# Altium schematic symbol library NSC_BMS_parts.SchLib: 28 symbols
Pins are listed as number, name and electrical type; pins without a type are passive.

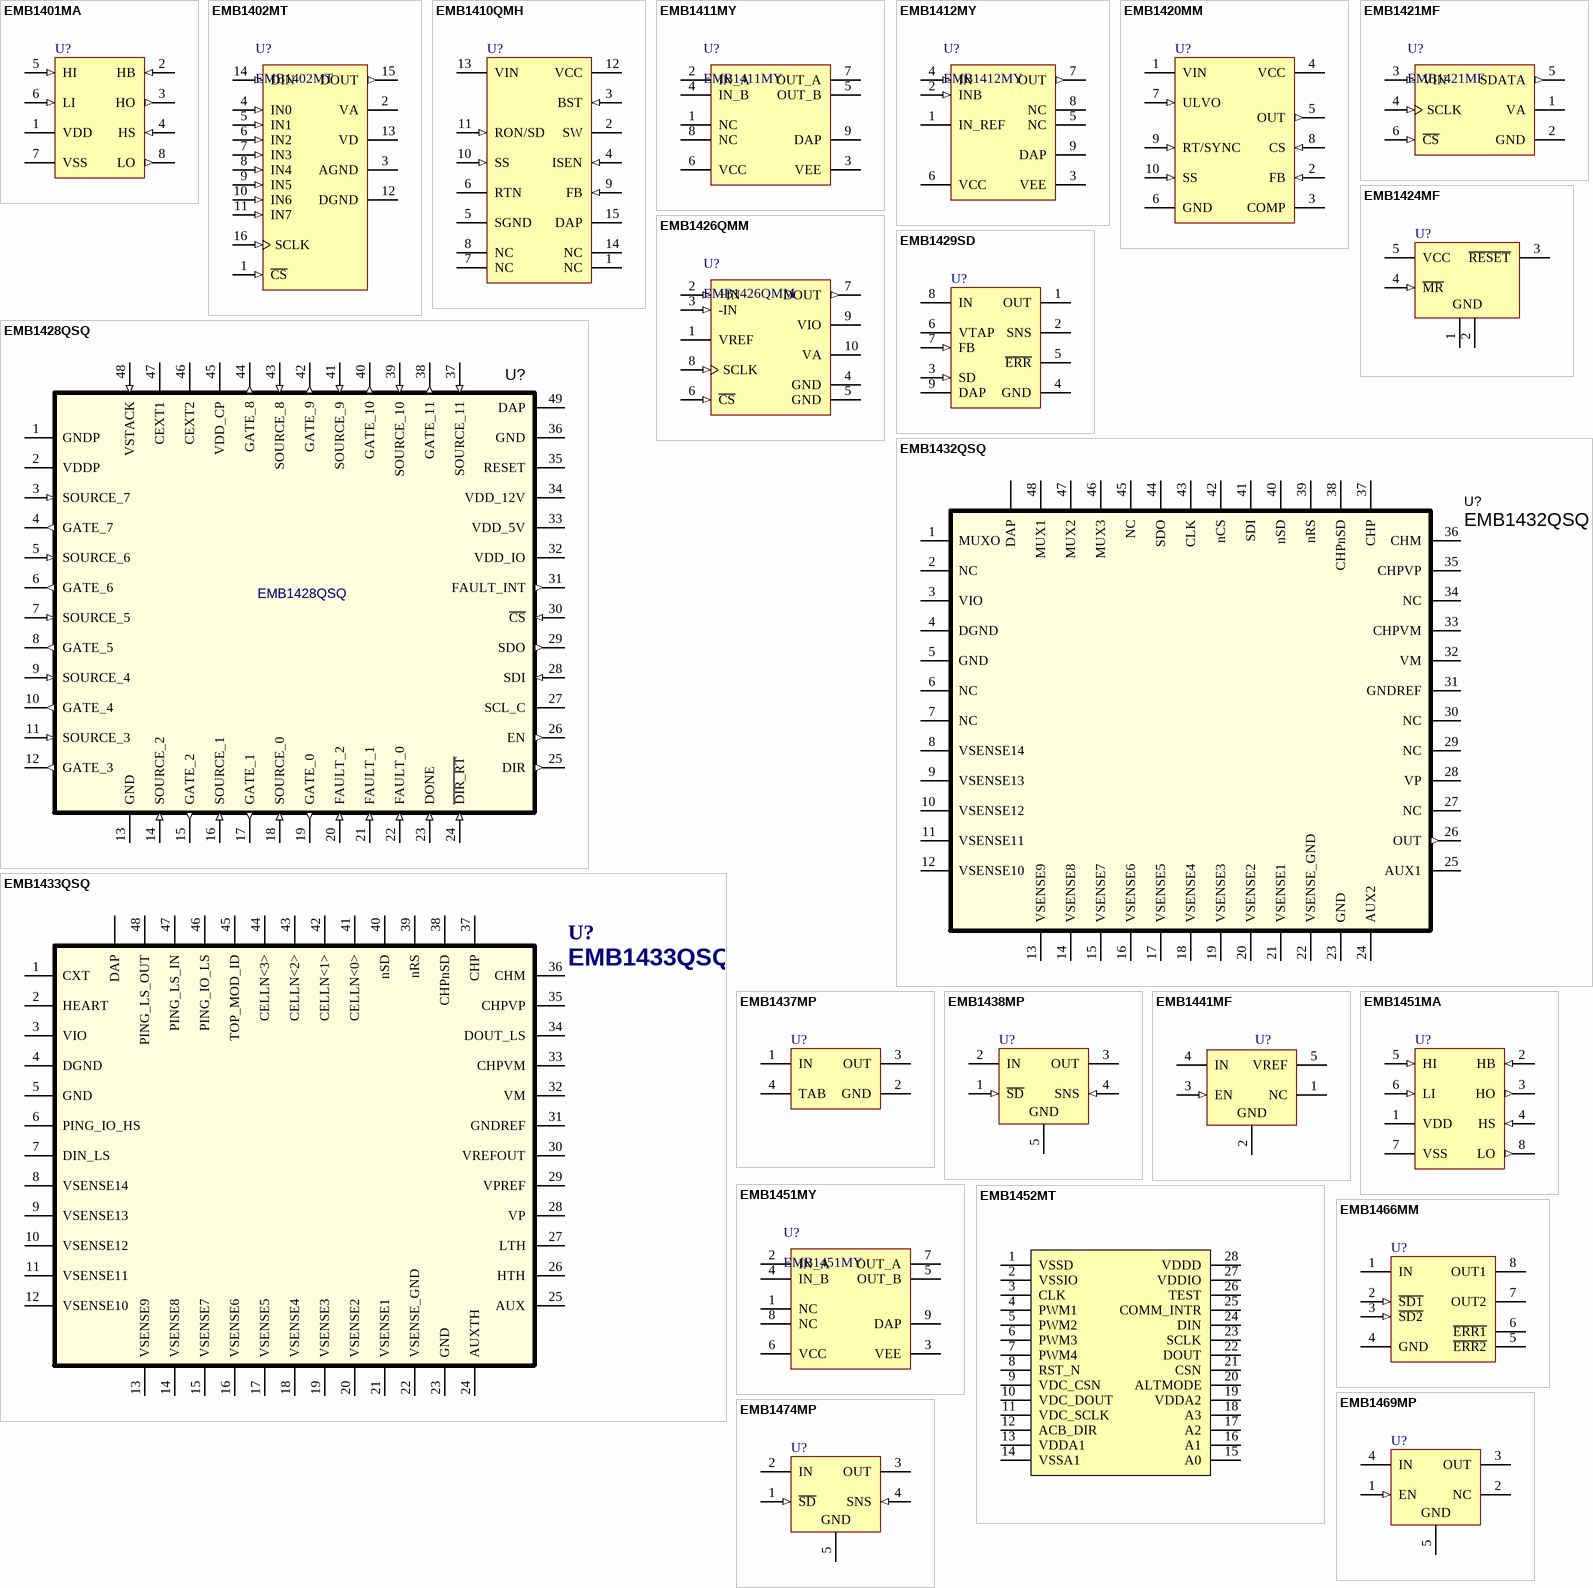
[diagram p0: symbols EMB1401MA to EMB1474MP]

## EMB1401MA
designator U?
3A High Voltage High-Side and Low-Side Gate Driver; PartNumber: EMB1401MA; Manufacturer: National Semiconductor; CompType: Switcher
footprint M08A_N (SOIC, 8-Leads, Body 4.9x3.9mm, Pitch 1.27mm, IPC Medium Density)
footprint M08A_L (SOIC, 8-Leads, Body 4.9x3.9mm, Pitch 1.27mm, IPC High Density)
footprint M08A_M (SOIC, 8-Leads, Body 4.9x3.9mm, Pitch 1.27mm, IPC Low Density)
pins: 1 VDD (power), 2 HB (in), 3 HO (out), 4 HS (in), 5 HI (in), 6 LI (in), 7 VSS (power), 8 LO (out)

## EMB1402MT
designator U?
8-Channel, 500 kSPS to 1 MSPS, 12-Bit A/D Converter; Manufacturer: National Semiconductor; CompType: ADC IC; PowerWise: Y
footprint MTC16_N (TSOP, 16-Leads, Body 5x4.4mm, Pitch 0.65mm, IPC Medium Density)
footprint MTC16_L (TSOP, 16-Leads, Body 5x4.4mm, Pitch 0.65mm, IPC High Density)
footprint MTC16_M (TSOP, 16-Leads, Body 5x4.4mm, Pitch 0.65mm, IPC Low Density)
pins: 1 ~{CS} (in), 2 VA (power), 3 AGND (power), 4 IN0 (in), 5 IN1 (in), 6 IN2 (in), 7 IN3 (in), 8 IN4 (in), 9 IN5 (in), 10 IN6 (in), 11 IN7 (in), 12 DGND (power), 13 VD (power), 14 DIN (in), 15 DOUT (out), 16 SCLK (in)

## EMB1410QMH
designator U?
High Voltage 1A Step Down Switching Regulator; PartNumber: EMB1410QMH; Manufacturer: National Semiconductor; CompType: Switcher
footprint MXA14A_N (TSOP, 14-Leads, Body 5x4.4mm, Pitch 0.65mm, Exposed Pad, IPC Medium Density)
footprint MXA14A_L (TSOP, 14-Leads, Body 5x4.4mm, Pitch 0.65mm, Exposed Pad, IPC High Density)
footprint MXA14A_M (TSOP, 14-Leads, Body 5x4.4mm, Pitch 0.65mm, Exposed Pad, IPC Low Density)
pins: 1 NC, 2 SW (power), 3 BST (in), 4 ISEN (in), 5 SGND (power), 6 RTN (power), 7 NC, 8 NC, 9 FB (in), 10 SS (in), 11 RON/SD (in), 12 VCC (power), 13 VIN (power), 14 NC, 15 DAP (power)

## EMB1411MY
designator U?
Dual 5A Compound Gate Driver; Manufacturer: National Semiconductor; CompType: Switcher; PackageTopMarking: ZXTT*SSYB; PowerWise: N
footprint MUY08A_N (TSOP, 8-Leads, Body 3x3mm, Pitch 0.65mm, Exposed Pad, IPC Medium Density)
footprint MUY08A_L (TSOP, 8-Leads, Body 3x3mm, Pitch 0.65mm, Exposed Pad, IPC High Density)
footprint MUY08A_M (TSOP, 8-Leads, Body 3x3mm, Pitch 0.65mm, Exposed Pad, IPC Low Density)
pins: 1 NC, 2 IN_A (power), 3 VEE (power), 4 IN_B (power), 5 OUT_B (power), 6 VCC (power), 7 OUT_A (power), 8 NC, 9 DAP (power)

## EMB1412MY
designator U?
Dual 5A Compound Gate Driver; Manufacturer: National Semiconductor; CompType: Switcher; PowerWise: N
footprint MUY08A_N (TSOP, 8-Leads, Body 3x3mm, Pitch 0.65mm, Exposed Pad, IPC Medium Density)
footprint MUY08A_L (TSOP, 8-Leads, Body 3x3mm, Pitch 0.65mm, Exposed Pad, IPC High Density)
footprint MUY08A_M (TSOP, 8-Leads, Body 3x3mm, Pitch 0.65mm, Exposed Pad, IPC Low Density)
pins: 1 IN_REF (power), 2 INB (in), 3 VEE (power), 4 IN (in), 5 NC, 6 VCC (power), 7 OUT (out), 8 NC, 9 DAP (power)

## EMB1420MM
designator U?
100V Current Mode PWM Controller; PartNumber: EMB1420MM; Manufacturer: National Semiconductor; CompType: Switcher
footprint MUB10A_N (TSSOP, 10-Leads, Body 3x3mm, Pitch 0.5mm, IPC Medium Density)
footprint MUB10A_L (TSSOP, 10-Leads, Body 3x3mm, Pitch 0.5mm, IPC High Density)
footprint MUB10A_M (TSSOP, 10-Leads, Body 3x3mm, Pitch 0.5mm, IPC Low Density)
pins: 1 VIN (power), 2 FB (in), 3 COMP, 4 VCC (power), 5 OUT (out), 6 GND (power), 7 ULVO (in), 8 CS (in), 9 RT/SYNC (in), 10 SS (in)

## EMB1421MF
designator U?
1MSPS, 12-Bit A/D Converter in SOT-23; Manufacturer: National Semiconductor; CompType: ADC IC; PowerWise: Y
footprint MF06A_N (SOT23, 6-Leads, Body 2.9x1.6mm, Pitch 0.95mm, Lead Span 2.8mm, IPC Medium Density)
footprint MF06A_L (SOT23, 6-Leads, Body 2.9x1.6mm, Pitch 0.95mm, Lead Span 2.8mm, IPC High Density)
footprint MF06A_M (SOT23, 6-Leads, Body 2.9x1.6mm, Pitch 0.95mm, Lead Span 2.8mm, IPC Low Density)
pins: 1 VA (power), 2 GND (power), 3 VIN (in), 4 SCLK (in), 5 SDATA (out), 6 ~{CS} (in)

## EMB1424MF
designator U?
5-Pin Microprocessor Reset Circuits; PartNumber: EMB1424MF; Manufacturer: National Semiconductor; CompType: MiscPower; PowerWise: N
footprint MF05A_N (SOT23, 5-Leads, Body 2.9x1.6mm, Pitch 0.95mm, Lead Span 2.8mm, IPC Medium Density)
footprint MF05A_L (SOT23, 5-Leads, Body 2.9x1.6mm, Pitch 0.95mm, Lead Span 2.8mm, IPC High Density)
footprint MF05A_M (SOT23, 5-Leads, Body 2.9x1.6mm, Pitch 0.95mm, Lead Span 2.8mm, IPC Low Density)
pins: 1 GND (power), 2 GND (power), 3 ~{RESET} (oc), 4 ~{MR} (in), 5 VCC (power)

## EMB1426QMM
designator U?
14-Bit, 50 kSPS to 250 kSPS, Differential Input, Micro Power A/D Converter; Manufacturer: National Semiconductor; CompType: ADC IC; PowerWise: Y
footprint MUB10A_N (TSSOP, 10-Leads, Body 3x3mm, Pitch 0.5mm, IPC Medium Density)
footprint MUB10A_L (TSSOP, 10-Leads, Body 3x3mm, Pitch 0.5mm, IPC High Density)
footprint MUB10A_M (TSSOP, 10-Leads, Body 3x3mm, Pitch 0.5mm, IPC Low Density)
pins: 1 VREF (power), 2 +IN (in), 3 -IN (in), 4 GND (power), 5 GND (power), 6 ~{CS} (in), 7 DOUT (out), 8 SCLK (in), 9 VIO (power), 10 VA (power)

## EMB1428QSQ
designator U?
12 channel Gate Controller; Manufacturer: National Semiconductor
footprint sqa48a (QFN, 48-Leads, Body 7x7mm, Pitch 0.5mm, NSC Recommended)
pins: 1 GNDP, 2 VDDP (power), 3 SOURCE_7 (in), 4 GATE_7 (out), 5 SOURCE_6 (in), 6 GATE_6 (out), 7 SOURCE_5 (in), 8 GATE_5 (out), 9 SOURCE_4 (in), 10 GATE_4 (out), 11 SOURCE_3 (in), 12 GATE_3 (out), 13 GND (power), 14 SOURCE_2 (in), 15 GATE_2 (out), 16 SOURCE_1 (in), 17 GATE_1 (out), 18 SOURCE_0 (in), 19 GATE_0 (out), 20 FAULT_2 (in), 21 FAULT_1 (in), 22 FAULT_0 (in), 23 DONE (in), 24 ~{DIR_RT} (in), 25 DIR (out), 26 EN (out), 27 SCL_C, 28 SDI (in), 29 SDO (out), 30 ~{CS} (in), 31 FAULT_INT (out), 32 VDD_IO (power), 33 VDD_5V (power), 34 VDD_12V (power), 35 RESET, 36 GND (power), 37 SOURCE_11 (in), 38 GATE_11 (out), 39 SOURCE_10 (in), 40 GATE_10 (out), 41 SOURCE_9 (in), 42 GATE_9 (out), 43 SOURCE_8 (in), 44 GATE_8 (out), 45 VDD_CP (power), 46 CEXT2, 47 CEXT1, 48 VSTACK (in), 49 DAP

## EMB1429SD
designator U?
Series of Adjustable Micropower Voltage Regulators; PartNumber: EMB1429SD; Manufacturer: National Semiconductor; CompType: LDO IC
footprint SDC08A (SON, 8-Leads, Body 4x4mm, Pitch 0.8mm, NSC Recommended)
pins: 1 OUT (power), 2 SNS, 3 SD (in), 4 GND (power), 5 ~{ERR} (oc), 6 VTAP, 7 FB (in), 8 IN (power), 9 DAP (power)

## EMB1432QSQ
designator U?
14 channel AFE; Manufacturer: National Semiconductor; CompType: Used in BOM report; SymbolCreator: cwiosc
footprint SQA48B (QFN, 48-Leads, Body 7x7mm, Pitch 0.5mm, NSC Recommended)
pins: 1 MUXO, 2 NC, 3 VIO, 4 DGND, 5 GND, 6 NC, 7 NC, 8 VSENSE14, 9 VSENSE13, 10 VSENSE12, 11 VSENSE11, 12 VSENSE10, 13 VSENSE9, 14 VSENSE8, 15 VSENSE7, 16 VSENSE6, 17 VSENSE5, 18 VSENSE4, 19 VSENSE3, 20 VSENSE2, 21 VSENSE1, 22 VSENSE_GND, 23 GND, 24 AUX2, 25 AUX1, 26 OUT (out), 27 NC, 28 VP, 29 NC, 30 NC, 31 GNDREF, 32 VM, 33 CHPVM, 34 NC, 35 CHPVP, 36 CHM, 37 CHP, 38 CHPnSD, 39 nRS, 40 nSD, 41 SDI, 42 nCS, 43 CLK, 44 SDO, 45 NC, 46 MUX3, 47 MUX2, 48 MUX1, 49 DAP

## EMB1433QSQ
designator U?
Battery Stack Protection WCOMP; Manufacturer: National Semiconductor; CompType: Used in BOM report; SymbolVersion: 100509; SymbolCreator: cwiosc
footprint sqa48b (QFN, 48-Leads, Body 7x7mm, Pitch 0.5mm, NSC Recommended)
pins: 1 CXT, 2 HEART, 3 VIO, 4 DGND, 5 GND, 6 PING_IO_HS, 7 DIN_LS, 8 VSENSE14, 9 VSENSE13, 10 VSENSE12, 11 VSENSE11, 12 VSENSE10, 13 VSENSE9, 14 VSENSE8, 15 VSENSE7, 16 VSENSE6, 17 VSENSE5, 18 VSENSE4, 19 VSENSE3, 20 VSENSE2, 21 VSENSE1, 22 VSENSE_GND, 23 GND, 24 AUXTH, 25 AUX, 26 HTH, 27 LTH, 28 VP, 29 VPREF, 30 VREFOUT, 31 GNDREF, 32 VM, 33 CHPVM, 34 DOUT_LS, 35 CHPVP, 36 CHM, 37 CHP, 38 CHPnSD, 39 nRS, 40 nSD, 41 CELLN<0>, 42 CELLN<1>, 43 CELLN<2>, 44 CELLN<3>, 45 TOP_MOD_ID, 46 PING_IO_LS, 47 PING_LS_IN, 48 PING_LS_OUT, 49 DAP

## EMB1437MP
designator U?
500 mA Low Dropout Regulator; PartNumber: EMB1437MP; Manufacturer: National Semiconductor; CompType: LDO IC; PowerWise: N
footprint MP04A_N (SOT223, 4-Leads, Body 6.5x3.5mm, Pitch 2.3mm, Lead Span 7mm, IPC Medium Density)
footprint MP04A_L (SOT223, 4-Leads, Body 6.5x3.5mm, Pitch 2.3mm, Lead Span 7mm, IPC High Density)
footprint MP04A_M (SOT223, 4-Leads, Body 6.5x3.5mm, Pitch 2.3mm, Lead Span 7mm, IPC Low Density)
pins: 1 IN (power), 2 GND (power), 3 OUT (power), 4 TAB (power)

## EMB1438MP
designator U?
0.8A Fast Ultra Low Dropout Linear Regulators; PartNumber: EMB1438MP; Manufacturer: National Semiconductor; CompType: LDO IC; PowerWise: N
footprint MP05A_N (SOT223, 5-Leads, Body 6.5x3.5mm, Pitch 1.5mm, Lead Span 7mm, IPC Medium Density)
footprint MP05A_L (SOT223, 5-Leads, Body 6.5x3.5mm, Pitch 1.5mm, Lead Span 7mm, IPC High Density)
footprint MP05A_M (SOT223, 5-Leads, Body 6.5x3.5mm, Pitch 1.5mm, Lead Span 7mm, IPC Low Density)
pins: 1 ~{SD} (in), 2 IN (power), 3 OUT (power), 4 SNS (in), 5 GND (power)

## EMB1441MF
designator U?
SOT-23 Precision Low Dropout Voltage Reference; PartNumber: EMB1441MF; Manufacturer: National Semiconductor; CompType: Voltage Reference IC; PowerWise: Y
footprint MF05A_N (SOT23, 5-Leads, Body 2.9x1.6mm, Pitch 0.95mm, Lead Span 2.8mm, IPC Medium Density)
footprint MF05A_L (SOT23, 5-Leads, Body 2.9x1.6mm, Pitch 0.95mm, Lead Span 2.8mm, IPC High Density)
footprint MF05A_M (SOT23, 5-Leads, Body 2.9x1.6mm, Pitch 0.95mm, Lead Span 2.8mm, IPC Low Density)
pins: 1 NC, 2 GND (power), 3 EN (in), 4 IN (power), 5 VREF (power)

## EMB1451MA
designator U?
1A High Voltage High-Side and Low-Side Gate Driver; PartNumber: EMB1451MA; Manufacturer: National Semiconductor; CompType: Switcher
footprint M08A_N (SOIC, 8-Leads, Body 4.9x3.9mm, Pitch 1.27mm, IPC Medium Density)
footprint M08A_L (SOIC, 8-Leads, Body 4.9x3.9mm, Pitch 1.27mm, IPC High Density)
footprint M08A_M (SOIC, 8-Leads, Body 4.9x3.9mm, Pitch 1.27mm, IPC Low Density)
pins: 1 VDD (power), 2 HB (in), 3 HO (out), 4 HS (in), 5 HI (in), 6 LI (in), 7 VSS (power), 8 LO (out)

## EMB1451MY
designator U?
Dual 5A Compound Gate Driver; Manufacturer: National Semiconductor; CompType: Switcher; PowerWise: N
footprint MUY08A_N (TSOP, 8-Leads, Body 3x3mm, Pitch 0.65mm, Exposed Pad, IPC Medium Density)
footprint MUY08A_L (TSOP, 8-Leads, Body 3x3mm, Pitch 0.65mm, Exposed Pad, IPC High Density)
footprint MUY08A_M (TSOP, 8-Leads, Body 3x3mm, Pitch 0.65mm, Exposed Pad, IPC Low Density)
pins: 1 NC, 2 IN_A (power), 3 VEE (power), 4 IN_B (power), 5 OUT_B (power), 6 VCC (power), 7 OUT_A (power), 8 NC, 9 DAP (power)

## EMB1452MT
designator U?
Manufacturer: National Semiconductor; CompType: Used in BOM report; SymbolVersion: use current date i.e. 2008-05-20; SymbolCreator: Use LDAP id
footprint MTC28_N (TSOP, 28-Leads, Body 9.7x4.4mm, Pitch 0.65mm, IPC Medium Density)
pins: 1 VSSD, 2 VSSIO, 3 CLK, 4 PWM1, 5 PWM2, 6 PWM3, 7 PWM4, 8 RST_N, 9 VDC_CSN, 10 VDC_DOUT, 11 VDC_SCLK, 12 ACB_DIR, 13 VDDA1, 14 VSSA1, 15 A0, 16 A1, 17 A2, 18 A3, 19 VDDA2, 20 ALTMODE, 21 CSN, 22 DOUT, 23 SCLK, 24 DIN, 25 COMM_INTR, 26 TEST, 27 VDDIO, 28 VDDD

## EMB1466MM
designator U?
Dual 150mA Ultra Low-Dropout Regulator; PartNumber: EMB1466MM; Manufacturer: National Semiconductor; CompType: LDO IC; PowerWise: N
footprint MUA08A_N (TSOP, 8-Leads, Body 3x3mm, Pitch 0.65mm, IPC Medium Density)
footprint MUA08A_L (TSOP, 8-Leads, Body 3x3mm, Pitch 0.65mm, IPC High Density)
footprint MUA08A_M (TSOP, 8-Leads, Body 3x3mm, Pitch 0.65mm, IPC Low Density)
pins: 1 IN (power), 2 ~{SD1} (in), 3 ~{SD2} (in), 4 GND (power), 5 ~{ERR2} (oc), 6 ~{ERR1} (oc), 7 OUT2 (power), 8 OUT1 (power)

## EMB1469MP
designator U?
500mA Low Dropout CMOS Linear Regulators; PartNumber: EMB1469MP; Manufacturer: National Semiconductor; CompType: LDO IC; PowerWise: Y
footprint MP05A_N (SOT223, 5-Leads, Body 6.5x3.5mm, Pitch 1.5mm, Lead Span 7mm, IPC Medium Density)
footprint MP05A_L (SOT223, 5-Leads, Body 6.5x3.5mm, Pitch 1.5mm, Lead Span 7mm, IPC High Density)
footprint MP05A_M (SOT223, 5-Leads, Body 6.5x3.5mm, Pitch 1.5mm, Lead Span 7mm, IPC Low Density)
pins: 1 EN (in), 2 NC, 3 OUT (power), 4 IN (power), 5 GND (power)

## EMB1474MP
designator U?
0.8A Fast Ultra Low Dropout Linear Regulators; PartNumber: EMB1474MP; Manufacturer: National Semiconductor; CompType: LDO IC; PowerWise: N
footprint MP05A_N (SOT223, 5-Leads, Body 6.5x3.5mm, Pitch 1.5mm, Lead Span 7mm, IPC Medium Density)
footprint MP05A_L (SOT223, 5-Leads, Body 6.5x3.5mm, Pitch 1.5mm, Lead Span 7mm, IPC High Density)
footprint MP05A_M (SOT223, 5-Leads, Body 6.5x3.5mm, Pitch 1.5mm, Lead Span 7mm, IPC Low Density)
pins: 1 ~{SD} (in), 2 IN (power), 3 OUT (power), 4 SNS (in), 5 GND (power)

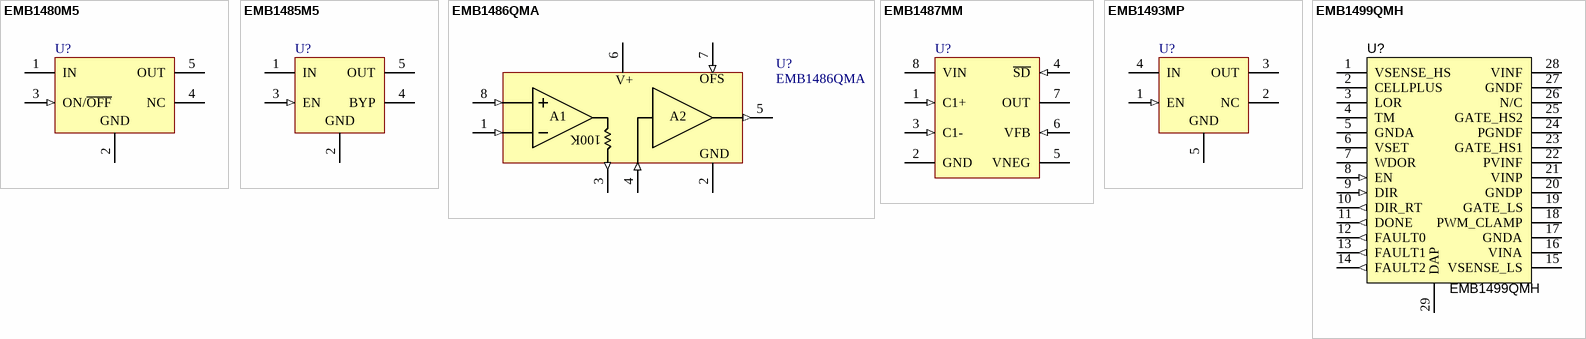
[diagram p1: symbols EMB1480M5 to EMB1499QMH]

## EMB1480M5
designator U?
Micropower 50 mA Ultra Low-Dropout Regulator In SOT-23 and micro SMD Packages; PartNumber: EMB1480M5; Manufacturer: National Semiconductor; CompType: LDO IC
footprint MF05A_N (SOT23, 5-Leads, Body 2.9x1.6mm, Pitch 0.95mm, Lead Span 2.8mm, IPC Medium Density)
footprint MF05A_L (SOT23, 5-Leads, Body 2.9x1.6mm, Pitch 0.95mm, Lead Span 2.8mm, IPC High Density)
footprint MF05A_M (SOT23, 5-Leads, Body 2.9x1.6mm, Pitch 0.95mm, Lead Span 2.8mm, IPC Low Density)
pins: 1 IN (power), 2 GND (power), 3 ON/~{OFF} (in), 4 NC, 5 OUT (power)

## EMB1485M5
designator U?
Micropower, 150mA Low-Noise Ultra Low-Dropout CMOS Voltage Regulator; PartNumber: EMB1485M5; Manufacturer: National Semiconductor; CompType: LDO IC; PowerWise: N
footprint MF05A_N (SOT23, 5-Leads, Body 2.9x1.6mm, Pitch 0.95mm, Lead Span 2.8mm, IPC Medium Density)
footprint MF05A_L (SOT23, 5-Leads, Body 2.9x1.6mm, Pitch 0.95mm, Lead Span 2.8mm, IPC High Density)
footprint MF05A_M (SOT23, 5-Leads, Body 2.9x1.6mm, Pitch 0.95mm, Lead Span 2.8mm, IPC Low Density)
pins: 1 IN (power), 2 GND (power), 3 EN (in), 4 BYP, 5 OUT (power)

## EMB1486QMA
designator U?
60V Common Mode, Bidirectional, Gain of 20 Current Sensing Amplifier; Manufacturer: National Semiconductor; CompType: OpAmp IC; TaMin_C: -40.0; TaMax_C: 125.0; PowerWise: N
3D model M08A
footprint M08A_L
footprint M08A_M
footprint M08A_N
simulation model LMP8601 (SUBCKT)
footprint M08A
pins: 1 IN- (in), 2 GND (power), 3 A1 (out), 4 A2 (in), 5 OUT (out), 6 V+ (power), 7 OFS (in), 8 IN+ (in)

## EMB1487MM
designator U?
Low Noise Regulated Switched Capacitor Voltage Inverter; PartNumber: EMB1487MM; Manufacturer: National Semiconductor; CompType: Switch Caps; PowerWise: N
footprint MUA08A_N (TSOP, 8-Leads, Body 3x3mm, Pitch 0.65mm, IPC Medium Density)
footprint MUA08A_L (TSOP, 8-Leads, Body 3x3mm, Pitch 0.65mm, IPC High Density)
footprint MUA08A_M (TSOP, 8-Leads, Body 3x3mm, Pitch 0.65mm, IPC Low Density)
pins: 1 C1+ (in), 2 GND (power), 3 C1- (in), 4 ~{SD} (in), 5 VNEG (power), 6 VFB (in), 7 OUT (power), 8 VIN (power)

## EMB1493MP
designator U?
500mA Low Dropout CMOS Linear Regulators; PartNumber: EMB1493MP; Manufacturer: National Semiconductor; CompType: LDO IC; PowerWise: Y
footprint MP05A_N (SOT223, 5-Leads, Body 6.5x3.5mm, Pitch 1.5mm, Lead Span 7mm, IPC Medium Density)
footprint MP05A_L (SOT223, 5-Leads, Body 6.5x3.5mm, Pitch 1.5mm, Lead Span 7mm, IPC High Density)
footprint MP05A_M (SOT223, 5-Leads, Body 6.5x3.5mm, Pitch 1.5mm, Lead Span 7mm, IPC Low Density)
pins: 1 EN (in), 2 NC, 3 OUT (power), 4 IN (power), 5 GND (power)

## EMB1499QMH
designator U?
PWM Controller; Manufacturer: National Semiconductor; CompType: Used in BOM report; SymbolVersion: use current date i.e. 2008-05-20; SymbolCreator: Use LDAP id
footprint MXA28A_M (TSOP, 28-Leads, Body 9.7x4.4mm, Pitch 0.65mm, Exposed Pad, IPC Low Density)
pins: 1 VSENSE_HS, 2 CELLPLUS, 3 LOR, 4 TM, 5 GNDA, 6 VSET, 7 WDOR, 8 EN (in), 9 DIR (in), 10 DIR_RT (out), 11 DONE (out), 12 FAULT0 (out), 13 FAULT1 (out), 14 FAULT2 (out), 15 VSENSE_LS, 16 VINA, 17 GNDA, 18 PWM_CLAMP, 19 GATE_LS, 20 GNDP, 21 VINP, 22 PVINF, 23 GATE_HS1, 24 PGNDF, 25 GATE_HS2, 26 N/C, 27 GNDF, 28 VINF, 29 DAP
